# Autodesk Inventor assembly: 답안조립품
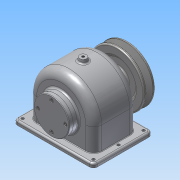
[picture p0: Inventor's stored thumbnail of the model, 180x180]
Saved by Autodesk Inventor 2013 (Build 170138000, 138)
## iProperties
Created: 2015-09
Part Number: 답안조립품
Document SubType Name: Assembly
Designer: Administrator
Author: Administrator
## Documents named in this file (14)
- C:\Users\Administrator\Desktop\450908V1012\답안조립품.iam
- C:\Users\Administrator\Desktop\450908V1012\본체.ipt
- C:\Users\Administrator\Desktop\450908V1012\축.ipt
- C:\Users\Administrator\Desktop\450908V1012\키 - 6 x 6 x 22.ipt
- C:\Users\Administrator\Desktop\450908V1012\키 - 5 x 5 x 18.ipt
- C:\Users\Administrator\Desktop\450908V1012\베어링 6203.ipt
- C:\Users\Administrator\Desktop\450908V1012\스퍼기어.ipt
- C:\Users\Administrator\Desktop\450908V1012\앞커버.ipt
- C:\Users\Administrator\Desktop\450908V1012\오일 실 17 32 8.ipt
- C:\Users\Administrator\Desktop\450908V1012\뒤커버.ipt
- C:\Users\Administrator\Desktop\450908V1012\V-벨트풀리.ipt
- C:\Users\Administrator\Desktop\450908V1012\멈춤나사 - M4x10.ipt
- C:\Users\Administrator\Desktop\450908V1012\볼트 M3 x 10.ipt
- C:\Users\Administrator\Desktop\450908V1012\볼트 M3 x 8.ipt
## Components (9 placed, 3 different names)
1. V-벨트풀리:1 — 각도:4
2. ISO 4762 M3 x 10:1
3. ISO 4762 M3 x 10:2
4. ISO 4762 M3 x 10:3
5. ISO 4762 M3 x 10:4
6. ISO 4762 M3 x 8:1
7. ISO 4762 M3 x 8:2
8. ISO 4762 M3 x 8:3
9. ISO 4762 M3 x 8:4
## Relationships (1: Angle 1)
- 각도:4 [Angle]: V-벨트풀리:1
